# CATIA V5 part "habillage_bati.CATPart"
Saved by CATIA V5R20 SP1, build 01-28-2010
Part number: habillage_bati
Bounding box of the stored display mesh (mm): x -60 to 60, y -859.958 to 140.805, z -307.699 to 143.509
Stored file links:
  C:\Users\patrice\Desktop\IFMa\Semestre 3\IAO\projet iao\iao\habillage_bati.CATPart
  C:\Users\patrice\Desktop\IFMa\Semestre 3\IAO\projet iao\iao\pcabanel.CATProduct
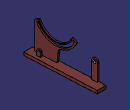
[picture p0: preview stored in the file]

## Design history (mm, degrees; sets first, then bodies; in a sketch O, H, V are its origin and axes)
External parameters (linked from other documents)
  External.AC = 200 mm
Set1
  Plane1: linked copy from another document
  DatumPoint1 "O": linked copy from another document
  Line1: linked copy from another document
  Point1 "batidroit": linked copy from another document
  Point2 "A": linked copy from another document
  Point3 "E": linked copy from another document
  Point4 "A": linked copy from another document
Set2
  Plane2 "Plan": type Offset, RefPlane Plane1, Offset 0
Body1 (main body)
  Sketch1 on Plane2, origin (0, 0, 0), H (0, 1, 0), V (0, 0, 1)
    arc A1 centre (-511.7052, 237.1789) radius 252 from (-735.2319, 120.8182) to (-288.1784, 120.8182) ccw
    point P1 (-511.7052, 237.1789)
    reference projected point E1 (-511.7052, 237.1789) from DatumPoint1
    arc A2 centre (-511.7052, 237.1789) radius 292 from (-770.7123, 102.3483) to (-252.698, 102.3483) ccw
    point P4 (-511.7052, 237.1789)
    point P5 (-770.7123, 102.3483)
    reference projected point E2 (-511.7052, 237.1789) from DatumPoint1
    construction line L1 (-288.1784, 120.8182) -> (-511.7052, 237.1789)
    construction line L2 (-735.2319, 120.8182) -> (-511.7052, 237.1789)
    construction line L3 (-770.7123, 102.3483) -> (-511.7052, 237.1789)
    construction line L4 (-252.698, 102.3483) -> (-511.7052, 237.1789)
    line L5 (-252.698, 102.3483) -> (-288.1784, 120.8182)
    line L6 (-770.7123, 102.3483) -> (-735.2319, 120.8182)
    construction line L7 (-511.7052, 237.1789) -> (-511.7052, -54.8211)
    point P7 (-511.7052, -54.8211)
    point P8 (-491.0656, -269.8521)
    line L8 (-491.0656, -269.8521) -> (-469.5443, -100.1421)
    point P9 (-465.9046, -71.4411)
    point P11 (-734.9579, 143.5085)
    line L9 (-734.9579, 143.5085) -> (-779.9473, 120.0885)
    line L10 (-790.7123, 102.3483) -> (-790.7123, -284.4067)
    line L11 (-790.7123, -284.4067) -> (-491.0656, -269.8521)
    arc A3 centre (-511.7052, 237.1789) radius 312 from (-439.1624, -66.2706) to (-226.292, 111.1498) ccw
    line L12 (-226.292, 111.1498) -> (-288.4525, 143.5085)
    arc A4 centre (-511.7052, 237.1789) radius 242.1072 from (-734.9579, 143.5085) to (-288.4525, 143.5085) ccw
    point P14 (-734.9579, 143.5085)
    reference projected line E3 (-699.9886, -280) -> (0, -246) from Line1
    reference projected line E4 (-699.9886, -280) -> (0, -246) from Line1
    arc A5 centre (-429.8621, -105.1743) radius 40 from (-439.1624, -66.2706) to (-469.5443, -100.1421) ccw
    arc A6 centre (-770.7123, 102.3483) radius 20 from (-790.7123, 102.3483) to (-779.9473, 120.0885) cw
    radius A1 = 252 {= 1.26*External.AC}
    radius A2 = 292 {= 1.46*External.AC}
    angle L4 L3 = 125
    angle L1 L2 = 125 {= Sketch1.angle(L4 L3)}
    length L5 = 40 {= 0.2*External.AC}
    angle L7 L5 = 62.5 {= Sketch1.angle(L1 L2) /2}
    distance A2 A3 = 20 {= External.AC /10}
    distance A4 A1 = 9.8928
    distance L12 L5 = 20 {= Sketch1.distance(A2 A3)}
    distance L9 L6 = 20 {= Sketch1.distance(A2 A3)}
    distance P5 L10 = 20 {= Sketch1.distance(A2 A3)}
    distance L11 E4 = 0
    length L11 = 300 {= 1.5*External.AC}
    distance P8 P9 = 200 {= External.AC}
    radius A5 = 40
    radius A6 = 20
    coincidence: E1 P1, E2 P4, P7 A2, P14 L9, A3 P9, L8 P9, P11 P14
    vertical: L7 V, L10 V
    parallelism: L11 E3
    tangency: A5 L8, A5 A3, A6 L10, A6 L9
  Pad1: profile Sketch1, direction (1, 0, 0), length -20 {= -External.AC /10.}, opposite side length 40 {= External.AC /5}
  Sketch2 on Plane2, origin (0, 0, 0), H (0, 1, 0), V (0, 0, 1)
    line L1 (-859.9576, -267.7465) -> (138.8648, -219.2314)
    line L2 (138.8648, -219.2314) -> (140.8054, -259.1843)
    line L3 (140.8054, -259.1843) -> (-858.017, -307.6994)
    line L4 (-858.017, -307.6994) -> (-859.9576, -267.7465)
    reference projected line E1 (-699.9886, -280) -> (0, -246) from Line1
    reference projected line E2 (-699.9886, -280) -> (0, -246) from Line1
    reference projected line E3 (-699.9886, -280) -> (0, -246) from Line1
    reference projected point E4 (0, -246) from Point1
    distance L1 L3 = 40 {= External.AC /5}
    distance E3 L3 = 20 {= Sketch2.distance(L1 L3) /2}
    length L3 = 1000 {= 5*External.AC}
    distance E4 L2 = 140 {= 0.7*External.AC}
    parallelism: L1 E1, L3 E2
    perpendicularity: L4 L1, L2 L1
  Pad2: profile Sketch2, direction (1, 0, 0), length 60 {= 0.3*External.AC}, opposite side length 60 {= 0.3*External.AC}
  Sketch3 on Plane2, origin (0, 0, 0), H (0, 1, 0), V (0, 0, 1)
    line L1 (40, -224.0335) -> (40, 0)
    arc A1 centre (0, 0) radius 40 from (40, 0) to (-40, 0) ccw
    point P3 (0, 0)
    line L2 (-40, 0) -> (-40, -227.9193)
    line L3 (-40, -227.9193) -> (40, -224.0335)
    reference projected point E1 (0, 0) from Point4
    reference projected line E2 (138.8648, -219.2314) -> (-859.9576, -267.7465) from edge [face of Pad2 from Sketch2.L1 | end face of Pad2]
    reference projected line E3 (-790.7123, 102.3483) -> (-790.7123, -284.4067) from edge [face of Pad1 from Sketch1.L10 | end face of Pad1]
    radius A1 = 40 {= External.AC /5}
    coincidence: P3 E1, E2 L3
    tangency: L1 A1, L2 A1
    parallelism: L1 L2, L2 E3
  Pad3: profile Sketch3, direction (1, 0, 0), length -40 {= -0.2*External.AC}, opposite side length 60 {= 0.3*External.AC}
  Sketch4 on start face of Pad3, origin (-60, 0, 0), H (0, -1, 0), V (0, 0, 1)
    point P1 (0, 0)
    reference projected point E1 (0, 0) from Point2
    coincidence: E1 P1
  Hole1: placed by Sketch4, at (-60, 0, 0) direction (1, 0, 0), diameter 40 {= External.AC /5}, through (limit type 6)
  Sketch5 on Plane2, origin (0, 0, 0), H (0, 1, 0), V (0, 0, 1)
    line L1 (-725.9886, -261.2393) -> (-725.9886, -200)
    arc A1 centre (-699.9886, -200) radius 26 from (-725.9886, -200) to (-673.9886, -200) cw
    point P3 (-699.9886, -200)
    line L2 (-673.9886, -200) -> (-673.9886, -258.7135)
    line L3 (-673.9886, -258.7135) -> (-725.9886, -261.2393)
    reference projected line E1 (138.8648, -219.2314) -> (-859.9576, -267.7465) from edge [face of Pad2 from Sketch2.L1 | end face of Pad2]
    reference projected point E2 (-699.9886, -200) from Point3
    reference projected line E3 (-790.7123, 102.3483) -> (-790.7123, -284.4067) from edge [face of Pad1 from Sketch1.L10 | end face of Pad1]
    radius A1 = 26 {= 0.13*External.AC}
    tangency: A1 L1, L2 A1
    coincidence: L3 E1, E2 P3
    parallelism: E3 L1, L2 L1
  Pad4: profile Sketch5, direction (1, 0, 0), length 20 {= 0.1*External.AC}
  Sketch6 on end face of Pad4, origin (20, -349.9943, -100), H (0, 1, 0), V (0, 0, 1)
    point P1 (-349.9943, -100)
    reference projected point E1 (-349.9943, -100) from Point3
    coincidence: E1 P1
  Hole2: placed by Sketch6, at (20, -699.9886, -200) direction (-1, 0, 0), diameter 20 {= 0.1*External.AC}, through (limit type 6)
Relations
  Sketch1.length(L5) = 0.2`Paramètres externes\AC` (deactivated)
  Sketch1.angle(L7 L5) = Sketch1.angle(L7 L5) /2 (deactivated)
  Hole1.Diameter = Hole1.Diameter (deactivated)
